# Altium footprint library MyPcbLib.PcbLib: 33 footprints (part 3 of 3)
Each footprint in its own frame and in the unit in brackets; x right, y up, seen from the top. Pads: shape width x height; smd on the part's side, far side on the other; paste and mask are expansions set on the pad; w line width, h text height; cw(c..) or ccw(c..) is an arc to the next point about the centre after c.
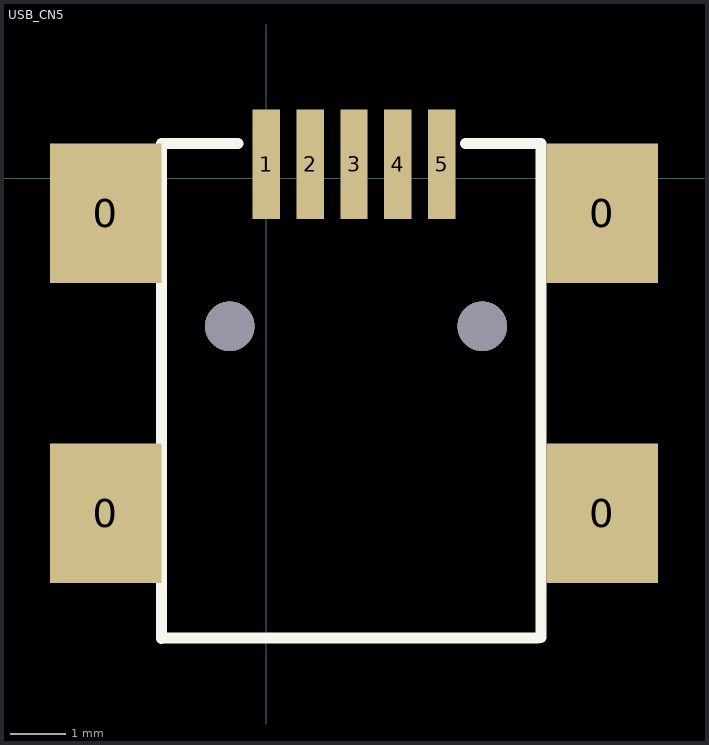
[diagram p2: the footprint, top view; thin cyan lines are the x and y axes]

## USB_CN5 [mil]
pads (9):
  rect 80x100 smd: 0(-115,-240) 0(-115,-25) 0(241,-240) 0(241,-25)
  rect 19.68x78.74 smd: 1(0,10) 2(31.5,10) 3(63,10) 4(94.5,10) 5(126,10)
via 155,-106 diameter 35.43 hole 35.43
via -26,-106 diameter 35.43 hole 35.43
Top Overlay:
  lines w7.87: -75,-330 -75,25 ; -74.8,-329.33 195,-329.33 ; -74.8,25 -20,25 ; 143,25 197,25 197,-329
